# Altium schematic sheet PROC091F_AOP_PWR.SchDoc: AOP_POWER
size 431 x 279 mm; Date: Not shown in title block; ApprovedBy: Not shown in title block; CheckedBy: Not shown in title block; Author: Not shown in title block; CompanyName: Not shown in title block; DrawnBy: Antony/Bala; Engineer: Not shown in title block; Organization: Not shown in title block; Address1: Not shown in title block; Address2: Not shown in title block; Address3: Not shown in title block; Address4: Not shown in title block; DocumentNumber: 4; Revision: Use project parameter SCH_Rev; SheetNumber: 4; SheetTotal: 12; PageSetup: Record=PageOptions¦CenterHorizontal=True¦CenterVertical=True¦PrintScale=1.00¦XCorrection=1.00¦YCorrection=1.00¦PrintKind=0¦BorderSize=5000000¦LeftOffset=0¦BottomOffset=0¦Orientation=2¦PaperLength=1000¦PaperWidth=1000¦Scale=100¦PaperSource=15¦PrintQuality=600¦MediaType=1¦DitherType=10¦PaperKind=Letter¦PrintScaleMode=1
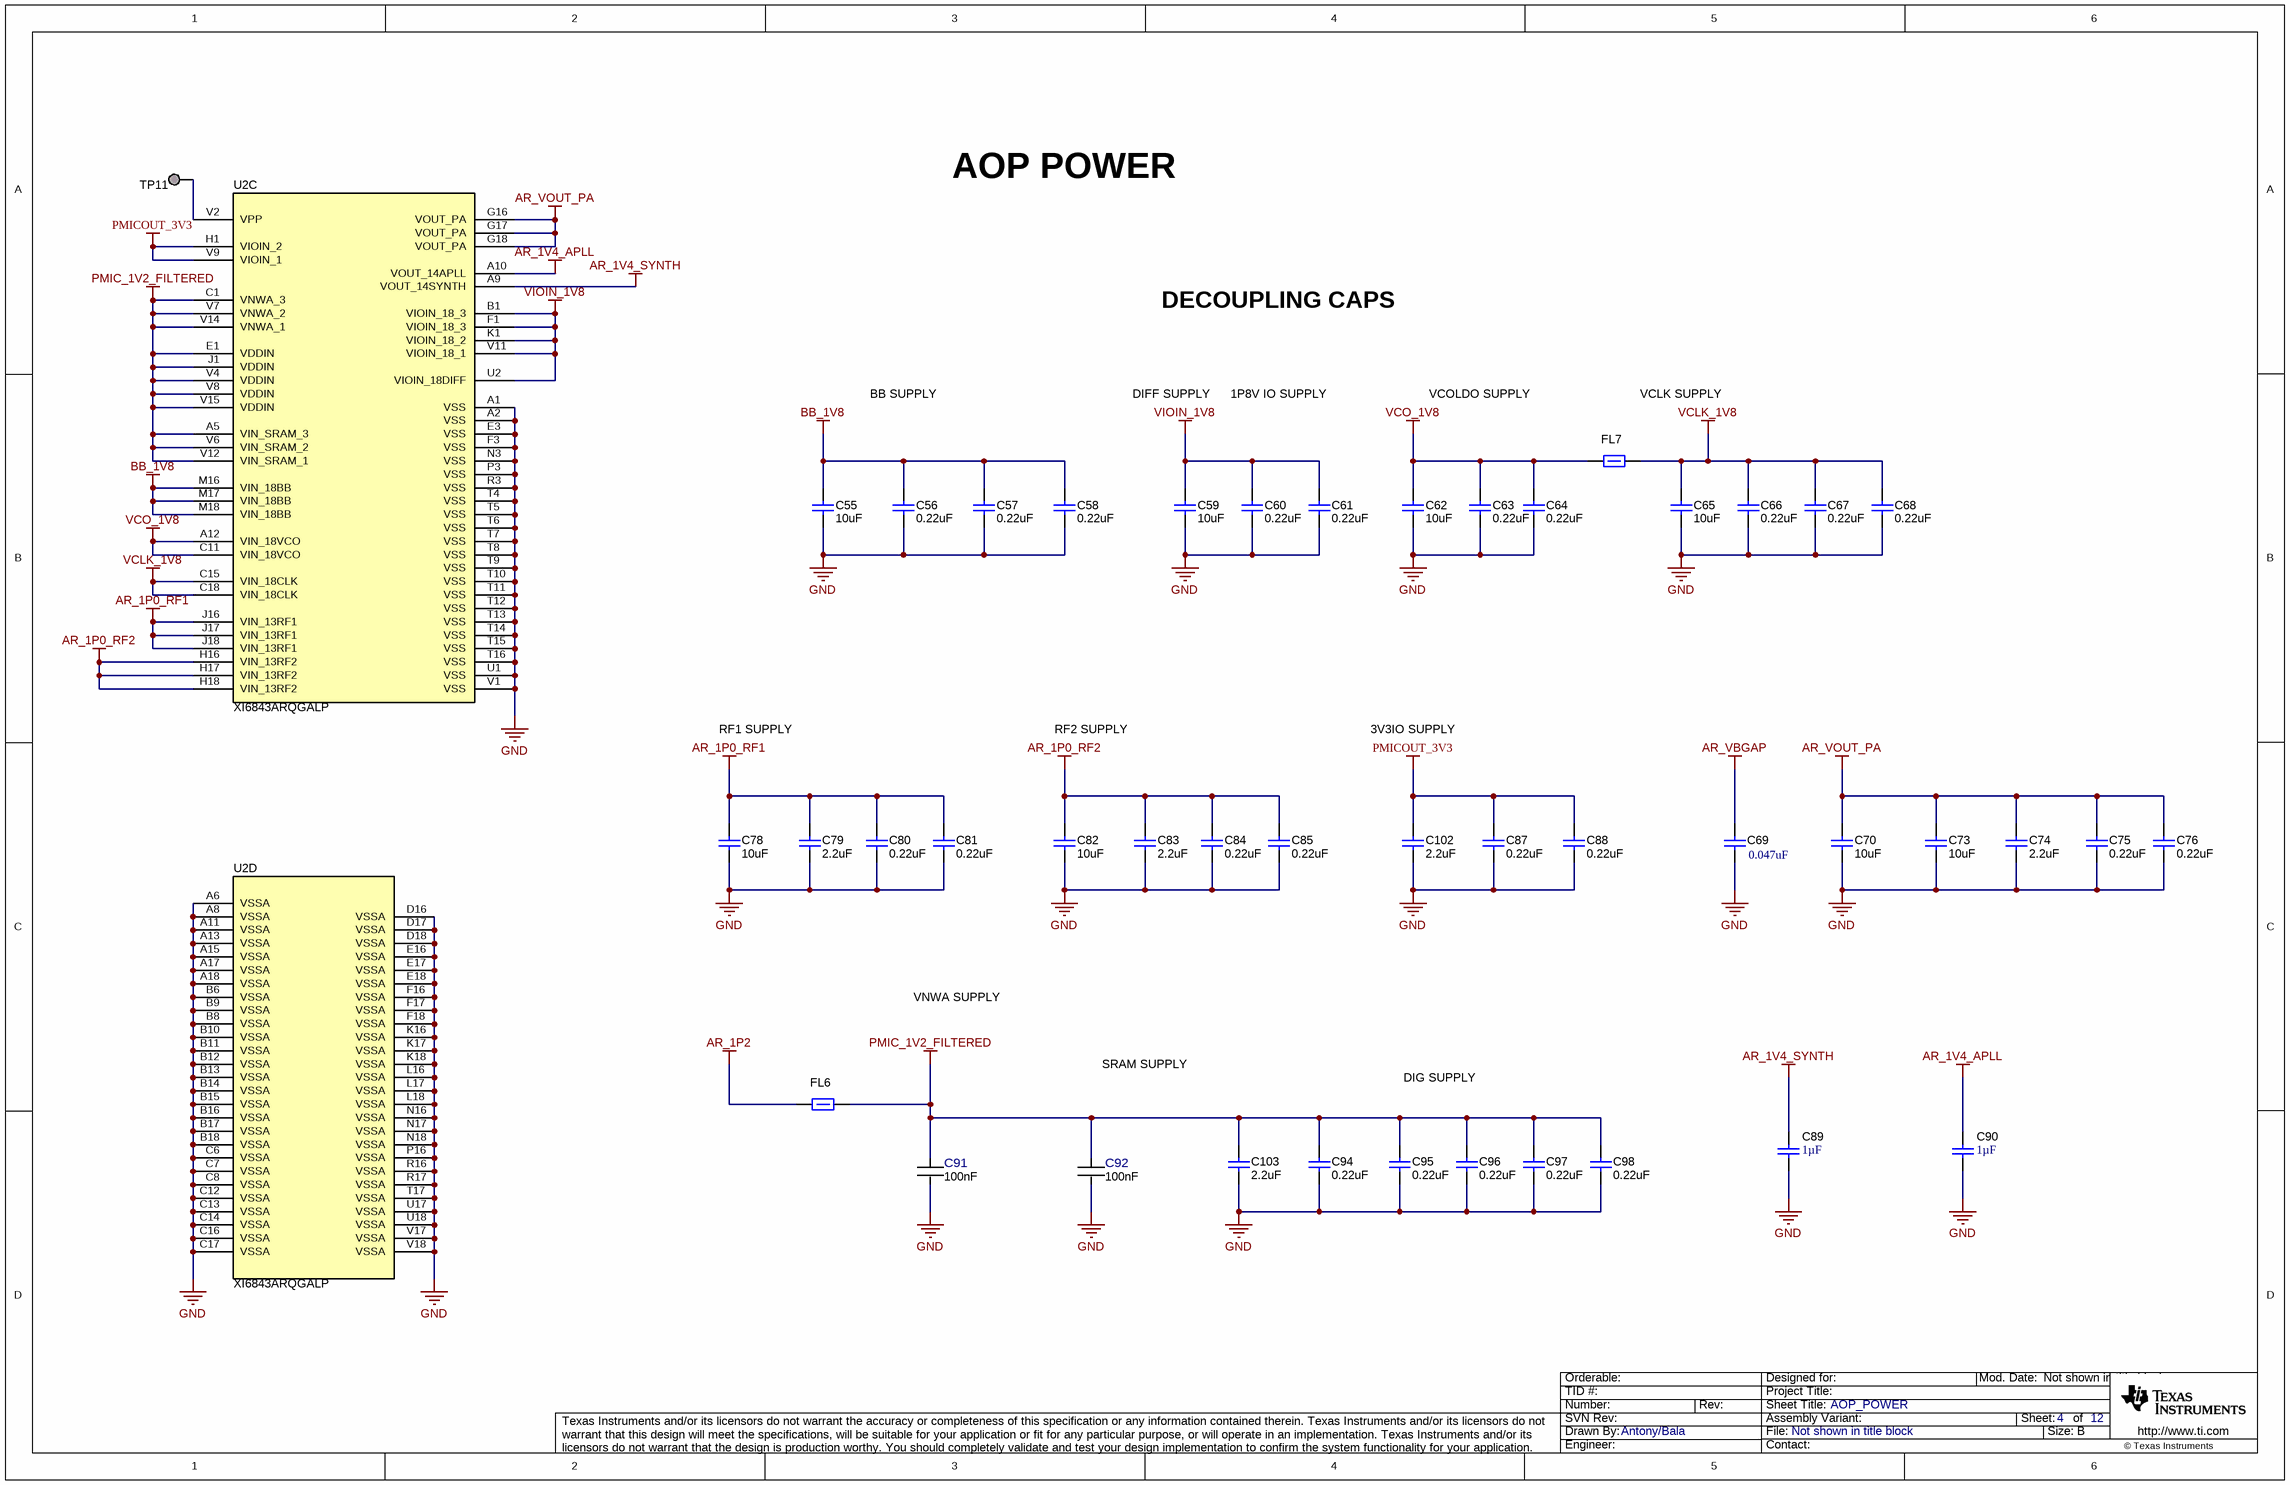
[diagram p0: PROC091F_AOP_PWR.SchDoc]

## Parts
C55  value 10uF  [0402_070]  (hidden comment: CL05A106MP5NUNC)
C56  value 0.22uF  [0201_033L]  (hidden comment: LMK063BJ224MP-F)
C57  value 0.22uF  [0201_033L]  (hidden comment: LMK063BJ224MP-F)
C58  value 0.22uF  [0201_033L]  (hidden comment: LMK063BJ224MP-F)
C59  value 10uF  [0402_070]  (hidden comment: CL05A106MP5NUNC)
C60  value 0.22uF  [0201_033L]  (hidden comment: LMK063BJ224MP-F)
C61  value 0.22uF  [0201_033L]  (hidden comment: LMK063BJ224MP-F)
C62  value 10uF  [0402_070]  (hidden comment: CL05A106MP5NUNC)
C63  value 0.22uF  [0201_033L]  (hidden comment: LMK063BJ224MP-F)
C64  value 0.22uF  [0201_033L]  (hidden comment: LMK063BJ224MP-F)
C65  value 10uF  [0402_070]  (hidden comment: CL05A106MP5NUNC)
C66  value 0.22uF  [0201_033L]  (hidden comment: LMK063BJ224MP-F)
C67  value 0.22uF  [0201_033L]  (hidden comment: LMK063BJ224MP-F)
C68  value 0.22uF  [0201_033L]  (hidden comment: LMK063BJ224MP-F)
C69  ValueDisplayed: 0.047uF  [0201_033L]  (hidden comment: GRM033R61C473KE84D)
C70  value 10uF  [0402_070]  (hidden comment: CL05A106MP5NUNC)
C73  value 10uF  [0402_070]  (hidden comment: CL05A106MP5NUNC)
C74  value 2.2uF  [0201L]  (hidden comment: CL03A225MQ3CRNC)
C75  value 0.22uF  [0201_033L]  (hidden comment: LMK063BJ224MP-F)
C76  value 0.22uF  [0201_033L]  (hidden comment: LMK063BJ224MP-F)
C78  value 10uF  [0402_070]  (hidden comment: CL05A106MP5NUNC)
C79  value 2.2uF  [0201L]  (hidden comment: CL03A225MQ3CRNC)
C80  value 0.22uF  [0201_033L]  (hidden comment: LMK063BJ224MP-F)
C81  value 0.22uF  [0201_033L]  (hidden comment: LMK063BJ224MP-F)
C82  value 10uF  [0402_070]  (hidden comment: CL05A106MP5NUNC)
C83  value 2.2uF  [0201L]  (hidden comment: CL03A225MQ3CRNC)
C84  value 0.22uF  [0201_033L]  (hidden comment: LMK063BJ224MP-F)
C85  value 0.22uF  [0201_033L]  (hidden comment: LMK063BJ224MP-F)
C87  value 0.22uF  [0201_033L]  (hidden comment: LMK063BJ224MP-F)
C88  value 0.22uF  [0201_033L]  (hidden comment: LMK063BJ224MP-F)
C89  ValueDisplayed: 1µF  [0402L]  (hidden comment: CGB2A1X6S0J105K033BC)
C90  ValueDisplayed: 1µF  [0402L]  (hidden comment: CGB2A1X6S0J105K033BC)
C91  Cap_F: 100nF  [FP-GRM033R6YA104KE14D_0201 (0603 Metric)-IPC_C]  (hidden comment: GRM033R6YA104KE14D)
C92  Cap_F: 100nF  [FP-GRM033R6YA104KE14D_0201 (0603 Metric)-IPC_C]  (hidden comment: GRM033R6YA104KE14D)
C94  value 0.22uF  [0201_033L]  (hidden comment: LMK063BJ224MP-F)
C95  value 0.22uF  [0201_033L]  (hidden comment: LMK063BJ224MP-F)
C96  value 0.22uF  [0201_033L]  (hidden comment: LMK063BJ224MP-F)
C97  value 0.22uF  [0201_033L]  (hidden comment: LMK063BJ224MP-F)
C98  value 0.22uF  [0201_033L]  (hidden comment: LMK063BJ224MP-F)
C102  value 2.2uF  [0201L]  (hidden comment: CL03A225MQ3CRNC)
C103  value 2.2uF  [0201L]  (hidden comment: CL03A225MQ3CRNC)
FL6  BLM15PD300SZ1D  [0402L]  (value not drawn)
FL7  BLM15PD300SZ1D  [0402L]  (value not drawn)
TP11  TESTPOINT  [TP_25MIL-SMT]  (value not drawn)  (no BOM)
U2  XI6843ARQGALP  [ALP0180A]  (parts C,D of 4)

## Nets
AR_1P0_RF1: C78.1 C79.1 C80.1 C81.1 U2.J16(VIN_13RF1) U2.J17(VIN_13RF1) U2.J18(VIN_13RF1)
AR_1P0_RF2: C82.1 C83.1 C84.1 C85.1 U2.H16(VIN_13RF2) U2.H17(VIN_13RF2) U2.H18(VIN_13RF2)
AR_1P2: FL6.1
AR_1V4_APLL: C90.1 U2.A10(VOUT_14APLL)
AR_1V4_SYNTH: C89.1 U2.A9(VOUT_14SYNTH)
AR_VBGAP: C69.1
AR_VOUT_PA: C70.1 C73.1 C74.1 C75.1 C76.1 U2.G16(VOUT_PA) U2.G17(VOUT_PA) U2.G18(VOUT_PA)
BB_1V8: C55.1 C56.1 C57.1 C58.1 U2.M16(VIN_18BB) U2.M17(VIN_18BB) U2.M18(VIN_18BB)
GND: C55.2 C56.2 C57.2 C58.2 C59.2 C60.2 C61.2 C62.2 C63.2 C64.2 C65.2 C66.2 C67.2 C68.2 C69.2 C70.2 C73.2 C74.2 C75.2 C76.2 C78.2 C79.2 C80.2 C81.2 C82.2 C83.2 C84.2 C85.2 C87.2 C88.2 C89.2 C90.2 C91.2 C92.2 C94.2 C95.2 C96.2 C97.2 C98.2 C102.2 C103.2 U2.A1(VSS) U2.A2(VSS) U2.A6(VSSA) U2.A8(VSSA) U2.A11(VSSA) U2.A13(VSSA) U2.A15(VSSA) U2.A17(VSSA) U2.A18(VSSA) U2.B6(VSSA) U2.B8(VSSA) U2.B9(VSSA) U2.B10(VSSA) U2.B11(VSSA) U2.B12(VSSA) U2.B13(VSSA) U2.B14(VSSA) U2.B15(VSSA) U2.B16(VSSA) U2.B17(VSSA) U2.B18(VSSA) U2.C6(VSSA) U2.C7(VSSA) U2.C8(VSSA) U2.C12(VSSA) U2.C13(VSSA) U2.C14(VSSA) U2.C16(VSSA) U2.C17(VSSA) U2.D16(VSSA) U2.D17(VSSA) U2.D18(VSSA) U2.E3(VSS) U2.E16(VSSA) U2.E17(VSSA) U2.E18(VSSA) U2.F3(VSS) U2.F16(VSSA) U2.F17(VSSA) U2.F18(VSSA) U2.K16(VSSA) U2.K17(VSSA) U2.K18(VSSA) U2.L16(VSSA) U2.L17(VSSA) U2.L18(VSSA) U2.N3(VSS) U2.N16(VSSA) U2.N17(VSSA) U2.N18(VSSA) U2.P3(VSS) U2.P16(VSSA) U2.R3(VSS) U2.R16(VSSA) U2.R17(VSSA) U2.T4(VSS) U2.T5(VSS) U2.T6(VSS) U2.T7(VSS) U2.T8(VSS) U2.T9(VSS) U2.T10(VSS) U2.T11(VSS) U2.T12(VSS) U2.T13(VSS) U2.T14(VSS) U2.T15(VSS) U2.T16(VSS) U2.T17(VSSA) U2.U1(VSS) U2.U17(VSSA) U2.U18(VSSA) U2.V1(VSS) U2.V17(VSSA) U2.V18(VSSA)
PMIC_1V2_FILTERED: C91.1 C92.1 C94.1 C95.1 C96.1 C97.1 C98.1 C103.1 FL6.2 U2.A5(VIN_SRAM_3) U2.C1(VNWA_3) U2.E1(VDDIN) U2.J1(VDDIN) U2.V4(VDDIN) U2.V6(VIN_SRAM_2) U2.V7(VNWA_2) U2.V8(VDDIN) U2.V12(VIN_SRAM_1) U2.V14(VNWA_1) U2.V15(VDDIN)
PMICOUT_3V3: C87.1 C88.1 C102.1 U2.H1(VIOIN_2) U2.V9(VIOIN_1)
VCLK_1V8: C65.1 C66.1 C67.1 C68.1 FL7.2 U2.C15(VIN_18CLK) U2.C18(VIN_18CLK)
VCO_1V8: C62.1 C63.1 C64.1 FL7.1 U2.A12(VIN_18VCO) U2.C11(VIN_18VCO)
VIOIN_1V8: C59.1 C60.1 C61.1 U2.B1(VIOIN_18_3) U2.F1(VIOIN_18_3) U2.K1(VIOIN_18_2) U2.U2(VIOIN_18DIFF) U2.V11(VIOIN_18_1)
NetTP11_1: TP11.1 U2.V2(VPP)

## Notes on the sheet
- AOP POWER
- DECOUPLING CAPS
- BB SUPPLY
- DIFF SUPPLY
- 1P8V IO SUPPLY
- VCOLDO SUPPLY
- VCLK SUPPLY
- RF1 SUPPLY
- RF2 SUPPLY
- 3V3IO SUPPLY
- VNWA SUPPLY
- SRAM SUPPLY
- DIG SUPPLY

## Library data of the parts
C55 C59 C62 C65 C70 C73 C78 C82 = CMP-0006339-4: CAP, CERM, 10 uF, 10 V, +/- 20%, X5R, 0402; Manufacturer: Samsung Electro-Mechanics; AEC Category: Q200; AEC Qualified: N; Cap_Case: 0402; Cap_F: 10µF; SizeArea_mm2: 0.5; SizeAreaWB_mm2: 3; SizeX_mm: 1; SizeZ_mm: 0.6; TaMax_C: 85°C; TaMin_C: -55°C; U/M: EA; Value1: Unknown; Value2: 10V
C56-C58 C60 C61 C63 C64 C66-C68 C75 C76 C80 C81 C84 C85 C87 C88 C94-C98 = CMP-0009781-1: CAP, CERM, 0.22 uF, 10 V, +/- 20%, X5R, 0201; Manufacturer: Taiyo Yuden; AEC Category: Q200; AEC Qualified: N; Cap_Case: 0201; Cap_F: 220nF; SizeArea_mm2: 0.18; SizeAreaWB_mm2: 2.08; SizeX_mm: 0.6; SizeY_mm: 0.3; SizeZ_mm: 0.33; TaMax_C: 85°C; TaMin_C: -55°C; U/M: EA; Value1: Unknown; Value2: 10V
C69 = CMP-0009718-2: CAP, CERM, 0.047 uF, 16 V, +/- 10%, X5R, 0201; Manufacturer: MuRata; TaMin_C: -55°C; Polarized: N; SizeAreaWB_mm2: 2.08; Value1: Unknown; U/M: EA; TaMax_C: 85°C; SizeZ_mm: 0.33; SizeX_mm: 0.6; SizeY_mm: 0.3; Cap_Case: 0201; Value2: 16V; SizeArea_mm2: 0.18; Cap_F: 47nF; AEC Category: Q200
C74 C79 C83 C102 C103 = CMP-0009657-3: CAP, CERM, 2.2 uF, 6.3 V, +/- 20%, X5R, 0201; Manufacturer: Samsung Electro-Mechanics; AEC Category: Q200; Cap_Case: 0201; Cap_F: 2.2µF; Polarized: N; SizeArea_mm2: 0.18; SizeAreaWB_mm2: 2.08; SizeX_mm: 0.6; SizeY_mm: 0.3; SizeZ_mm: 0.26; TaMax_C: 85°C; TaMin_C: -55°C; U/M: EA; Value1: Unknown; Value2: 6.3V
C89 C90 = CMP-0081763-1: CAP, CERM, 1 µF, 6.3 V,+/- 10%, X6S, 0402; Manufacturer: TDK; TaMin_C: -55°C; Polarized: N; SizeAreaWB_mm2: 3; U/M: EA; Value: 1uF; TaMax_C: 105°C; SizeZ_mm: 0.6; SizeX_mm: 1; SizeY_mm: 0.5; Cap_Case: 0402; Value2: 6.3V; CompType: Capacitor; AEC Category: Q200
C91 C92 = CMP-0086440-1: Cap Ceramic 0.1uF 35V X5R 10% Pad SMD 0201 85C T/R; Manufacturer: Murata Electronics North America; AEC Qualified: No; SizeZ_mm: 0.33mm; Symbol Name: SYM-GRM033R6YA104KE14D; TempCo: 15%
FL6 FL7 = CMP-0078934-1: Inductor, Ferrite Bead, Ferrite, 2.2 A, 0.035 ohm, AEC-Q200 Grade 1, SMD; Manufacturer: MuRata; AEC Category: Q200; AEC Grade: 1; AEC Qualified: Y; DCR_ohm: 0.035; Imax_A: 2.2A; SizeArea_mm2: 0.5; SizeAreaWB_mm2: 3; SizeZ_mm: 0.6
TP11 = CMP-0078143-3: TEST POINT.  No entry in BOM.
U2 = CMP-0860942-2: XI6843ARQGALP, ALP0180A (BGA-180); Manufacturer: Texas Instruments; SizeZ_mm: 0.965; SizeX_mm: 15; AEC Qualified: N; SizeArea_mm2: 225; SizeAreaWB_mm2: 289; CompType: IC; AEC Category: Q200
